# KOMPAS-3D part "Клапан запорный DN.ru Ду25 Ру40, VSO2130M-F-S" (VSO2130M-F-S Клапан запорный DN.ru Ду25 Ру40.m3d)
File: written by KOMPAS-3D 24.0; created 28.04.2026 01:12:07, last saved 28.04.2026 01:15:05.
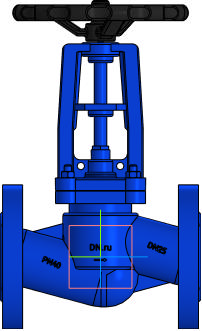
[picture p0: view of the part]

Document properties: Автор: DN.ru; Полное имя файла: C:\Работа\ГОТОВЫЕ ИСХОДНИКИ\VSO2130M-F-S Клапан запорный сильфонный DN.ru Ду15-100 Ру40\DN25\VSO2130M-F-S Клапан запорный DN.ru Ду25 Ру40.m3d

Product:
- Part/product: Клапан запорный DN.ru Ду25 Ру40  | designation VSO2130M-F-S
    Масса: 6
    Раздел спецификации: Прочие изделия
    Примечание: D090-01972

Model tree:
1. Операция без истории:1  (labels: SHAPEOBJECT3D_ATTR_BUTT)

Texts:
  VSO2130M-F-S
